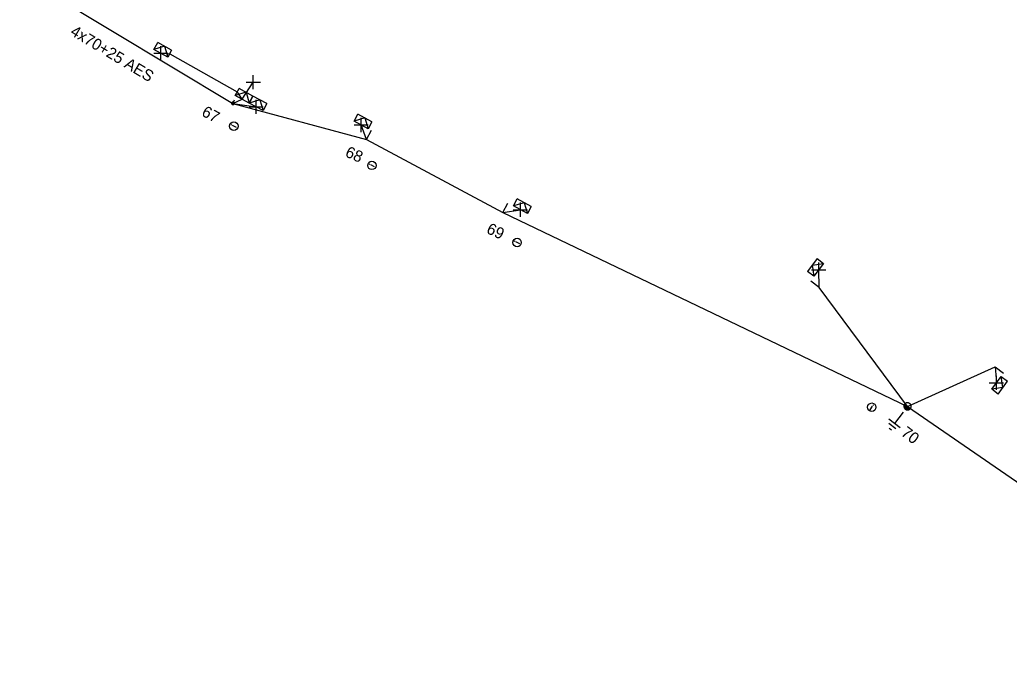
# Model space of a CAD drawing. Extents: x -540247 to -537390, y -1183887 to -1180355.
# Drawn here: x -537694.3 to -537607.2, y -1180598.3 to -1180542.1 of the extents above; entities that cross this region are included whole.
import ezdxf

# ---------------------------------------------------------------- set-up
doc = ezdxf.new("R2010")
doc.units = 0
for name, color, linetype in [('Vrstva 1', 7, 'Continuous'), ('Vrstva 10', 7, 'Continuous'), ('Vrstva 13', 7, 'Continuous'), ('Vrstva 14', 7, 'Continuous'), ('Vrstva 15', 7, 'Continuous'), ('Vrstva 2', 7, 'Continuous'), ('Vrstva 31', 7, 'Continuous'), ('Vrstva 34', 7, 'Continuous'), ('Vrstva 36', 7, 'Continuous'), ('Vrstva 4', 7, 'Continuous'), ('Vrstva 50', 7, 'Continuous'), ('Vrstva 51', 7, 'Continuous'), ('Vrstva 54', 7, 'Continuous'), ('Vrstva 59', 7, 'Continuous'), ('Vrstva 8', 7, 'Continuous'), ('Vrstva 9', 7, 'Continuous')]:
    doc.layers.add(name, color=color, linetype=linetype)

# ---------------------------------------------------------------- blocks, each defined once
blk = doc.blocks.new('NN440')
at = {"layer": 'Vrstva 2'}
for points in [[(0.63, 0), (0.63, 0.06), (0.62, 0.13), (0.6, 0.19), (0.58, 0.25), (0.55, 0.31), (0.51, 0.37), (0.47, 0.42), (0.42, 0.46), (0.37, 0.51), (0.32, 0.54), (0.26, 0.57), (0.2, 0.59), (0.13, 0.61), (0.07, 0.62), (0, 0.63), (-0.06, 0.62), (-0.13, 0.61), (-0.19, 0.59), (-0.26, 0.57), (-0.31, 0.54), (-0.37, 0.51), (-0.42, 0.46), (-0.47, 0.42), (-0.51, 0.37), (-0.54, 0.31), (-0.57, 0.25), (-0.6, 0.19), (-0.62, 0.13), (-0.63, 0.06), (-0.63, 0), (-0.63, -0.07), (-0.62, -0.14), (-0.6, -0.2), (-0.57, -0.26), (-0.54, -0.32), (-0.51, -0.37), (-0.47, -0.43), (-0.42, -0.47), (-0.37, -0.51), (-0.31, -0.55), (-0.26, -0.58), (-0.19, -0.6), (-0.13, -0.62), (-0.06, -0.63), (0, -0.63), (0.07, -0.63), (0.13, -0.62), (0.2, -0.6), (0.26, -0.58), (0.32, -0.55), (0.37, -0.51), (0.42, -0.47), (0.47, -0.43), (0.51, -0.37), (0.55, -0.32), (0.58, -0.26), (0.6, -0.2), (0.62, -0.14), (0.63, -0.07), (0.63, 0)], [(-0.63, 0), (0.63, 0)], [(-0.6, -0.18), (0.57, -0.18)], [(-0.51, -0.32), (0.5, -0.32)], [(-0.37, -0.47), (0.35, -0.47)]]:
    blk.add_lwpolyline(points, dxfattribs=at)
blk = doc.blocks.new('NN770')
at = {"layer": 'Vrstva 10'}
for p, q in [((0.002, 0.187), (0.002, 0.263)), ((0.002, -0.276), (0.002, 0.111))]:
    blk.add_line(p, q, dxfattribs=at)
blk.add_circle((0, -0.008), 0.375, dxfattribs=at)
blk = doc.blocks.new('NN800')
at = {"layer": 'Vrstva 1'}
for points in [[(-0.442, 0.442), (0.442, -0.442)], [(-0.442, -0.442), (0.442, 0.442)]]:
    blk.add_lwpolyline(points, dxfattribs=at)
blk = doc.blocks.new('NN630')
at = {"layer": 'Vrstva 9'}
for points in [[(-0.003, -0.7), (-0.703, 0)], [(-0.703, -0.7), (-0.703, 0), (0.697, 0), (0.697, -0.7)], [(-0.703, -0.7), (0.697, -0.7)], [(-0.003, -0.7), (0.697, 0)]]:
    blk.add_lwpolyline(points, dxfattribs=at)
blk = doc.blocks.new('NN810')
at = {"layer": 'Vrstva 14'}
for points in [[(0.004, -0.64), (0.004, -1.89)], [(0.629, -1.89), (-0.621, -1.89)], [(0.388, -2.2), (-0.399, -2.2)], [(0.004, -2.515), (-0.124, -2.515)], [(0.137, -2.515), (0.004, -2.515)]]:
    blk.add_lwpolyline(points, dxfattribs=at)
blk = doc.blocks.new('NN500')
at = {"layer": 'Vrstva 2'}
for points in [[(0, -0.24), (0.02, -0.23), (0.05, -0.23), (0.07, -0.22), (0.09, -0.22), (0.12, -0.2), (0.14, -0.19), (0.16, -0.18), (0.17, -0.16), (0.19, -0.14), (0.2, -0.12), (0.21, -0.1), (0.22, -0.07), (0.23, -0.05), (0.23, -0.02), (0.23, 0), (0.23, 0.02), (0.23, 0.05), (0.22, 0.07), (0.21, 0.1), (0.2, 0.12), (0.19, 0.14), (0.17, 0.16), (0.16, 0.17), (0.14, 0.19), (0.12, 0.2), (0.09, 0.21), (0.07, 0.22), (0.05, 0.23), (0.02, 0.23), (0, 0.23), (-0.03, 0.23), (-0.05, 0.23), (-0.07, 0.22), (-0.1, 0.21), (-0.12, 0.2), (-0.14, 0.19), (-0.16, 0.17), (-0.18, 0.16), (-0.19, 0.14), (-0.2, 0.12), (-0.22, 0.1), (-0.22, 0.07), (-0.23, 0.05), (-0.23, 0.02), (-0.24, 0), (-0.23, -0.02), (-0.23, -0.05), (-0.22, -0.07), (-0.22, -0.1), (-0.2, -0.12), (-0.19, -0.14), (-0.18, -0.16), (-0.16, -0.18), (-0.14, -0.19), (-0.12, -0.2), (-0.1, -0.22), (-0.07, -0.22), (-0.05, -0.23), (-0.03, -0.23), (0, -0.24)], [(0, -0.24), (0.02, -0.23), (0.05, -0.23), (0.07, -0.22), (0.09, -0.22), (0.12, -0.2), (0.14, -0.19), (0.16, -0.18), (0.17, -0.16), (0.19, -0.14), (0.2, -0.12), (0.21, -0.1), (0.22, -0.07), (0.23, -0.05), (0.23, -0.02), (0.23, 0), (0.23, 0.02), (0.23, 0.05), (0.22, 0.07), (0.21, 0.1), (0.2, 0.12), (0.19, 0.14), (0.17, 0.16), (0.16, 0.17), (0.14, 0.19), (0.12, 0.2), (0.09, 0.21), (0.07, 0.22), (0.05, 0.23), (0.02, 0.23), (0, 0.23), (-0.03, 0.23), (-0.05, 0.23), (-0.07, 0.22), (-0.1, 0.21), (-0.12, 0.2), (-0.14, 0.19), (-0.16, 0.17), (-0.18, 0.16), (-0.19, 0.14), (-0.2, 0.12), (-0.22, 0.1), (-0.22, 0.07), (-0.23, 0.05), (-0.23, 0.02), (-0.24, 0), (-0.23, -0.02), (-0.23, -0.05), (-0.22, -0.07), (-0.22, -0.1), (-0.2, -0.12), (-0.19, -0.14), (-0.18, -0.16), (-0.16, -0.18), (-0.14, -0.19), (-0.12, -0.2), (-0.1, -0.22), (-0.07, -0.22), (-0.05, -0.23), (-0.03, -0.23), (0, -0.24)], [(0, -0.21), (0.02, -0.2), (0.04, -0.2), (0.06, -0.2), (0.08, -0.19), (0.1, -0.18), (0.12, -0.17), (0.14, -0.15), (0.15, -0.14), (0.16, -0.12), (0.18, -0.1), (0.19, -0.08), (0.19, -0.06), (0.2, -0.04), (0.2, -0.02), (0.2, 0), (0.2, 0.02), (0.2, 0.04), (0.19, 0.06), (0.19, 0.08), (0.18, 0.1), (0.16, 0.12), (0.15, 0.14), (0.14, 0.15), (0.12, 0.17), (0.1, 0.18), (0.08, 0.19), (0.06, 0.19), (0.04, 0.2), (0.02, 0.2), (0, 0.2), (-0.02, 0.2), (-0.04, 0.2), (-0.06, 0.19), (-0.08, 0.19), (-0.1, 0.18), (-0.12, 0.17), (-0.14, 0.15), (-0.15, 0.14), (-0.17, 0.12), (-0.18, 0.1), (-0.19, 0.08), (-0.2, 0.06), (-0.2, 0.04), (-0.21, 0.02), (-0.21, 0), (-0.21, -0.02), (-0.2, -0.04), (-0.2, -0.06), (-0.19, -0.08), (-0.18, -0.1), (-0.17, -0.12), (-0.15, -0.14), (-0.14, -0.15), (-0.12, -0.17), (-0.1, -0.18), (-0.08, -0.19), (-0.06, -0.2), (-0.04, -0.2), (-0.02, -0.2), (0, -0.21)], [(0, -0.18), (0.02, -0.18), (0.04, -0.17), (0.05, -0.17), (0.07, -0.16), (0.09, -0.15), (0.1, -0.14), (0.12, -0.13), (0.13, -0.12), (0.14, -0.1), (0.15, -0.09), (0.16, -0.07), (0.17, -0.05), (0.17, -0.04), (0.17, -0.02), (0.17, 0), (0.17, 0.02), (0.17, 0.04), (0.17, 0.05), (0.16, 0.07), (0.15, 0.09), (0.14, 0.1), (0.13, 0.12), (0.12, 0.13), (0.1, 0.14), (0.09, 0.15), (0.07, 0.16), (0.05, 0.17), (0.04, 0.17), (0.02, 0.17), (0, 0.18), (-0.02, 0.17), (-0.04, 0.17), (-0.06, 0.17), (-0.07, 0.16), (-0.09, 0.15), (-0.1, 0.14), (-0.12, 0.13), (-0.13, 0.12), (-0.14, 0.1), (-0.15, 0.09), (-0.16, 0.07), (-0.17, 0.05), (-0.17, 0.04), (-0.18, 0.02), (-0.18, 0), (-0.18, -0.02), (-0.17, -0.04), (-0.17, -0.05), (-0.16, -0.07), (-0.15, -0.09), (-0.14, -0.1), (-0.13, -0.12), (-0.12, -0.13), (-0.1, -0.14), (-0.09, -0.15), (-0.07, -0.16), (-0.06, -0.17), (-0.04, -0.17), (-0.02, -0.18), (0, -0.18)], [(0, -0.15), (0.01, -0.15), (0.03, -0.14), (0.04, -0.14), (0.06, -0.13), (0.07, -0.13), (0.08, -0.12), (0.1, -0.11), (0.11, -0.1), (0.12, -0.09), (0.13, -0.07), (0.13, -0.06), (0.14, -0.05), (0.14, -0.03), (0.14, -0.02), (0.14, 0), (0.14, 0.01), (0.14, 0.03), (0.14, 0.04), (0.13, 0.06), (0.13, 0.07), (0.12, 0.09), (0.11, 0.1), (0.1, 0.11), (0.08, 0.12), (0.07, 0.13), (0.06, 0.13), (0.04, 0.14), (0.03, 0.14), (0.01, 0.14), (0, 0.15), (-0.02, 0.14), (-0.03, 0.14), (-0.05, 0.14), (-0.06, 0.13), (-0.07, 0.13), (-0.09, 0.12), (-0.1, 0.11), (-0.11, 0.1), (-0.12, 0.09), (-0.13, 0.07), (-0.13, 0.06), (-0.14, 0.04), (-0.14, 0.03), (-0.15, 0.01), (-0.15, 0), (-0.15, -0.02), (-0.14, -0.03), (-0.14, -0.05), (-0.13, -0.06), (-0.13, -0.07), (-0.12, -0.09), (-0.11, -0.1), (-0.1, -0.11), (-0.09, -0.12), (-0.07, -0.13), (-0.06, -0.13), (-0.05, -0.14), (-0.03, -0.14), (-0.02, -0.15), (0, -0.15)], [(0, -0.12), (0.01, -0.12), (0.02, -0.11), (0.03, -0.11), (0.05, -0.11), (0.06, -0.1), (0.07, -0.09), (0.08, -0.09), (0.09, -0.08), (0.09, -0.07), (0.1, -0.06), (0.11, -0.05), (0.11, -0.04), (0.11, -0.02), (0.11, -0.01), (0.12, 0), (0.11, 0.01), (0.11, 0.02), (0.11, 0.04), (0.11, 0.05), (0.1, 0.06), (0.09, 0.07), (0.09, 0.08), (0.08, 0.09), (0.07, 0.09), (0.06, 0.1), (0.05, 0.11), (0.03, 0.11), (0.02, 0.11), (0.01, 0.12), (0, 0.12), (-0.01, 0.12), (-0.03, 0.11), (-0.04, 0.11), (-0.05, 0.11), (-0.06, 0.1), (-0.07, 0.09), (-0.08, 0.09), (-0.09, 0.08), (-0.1, 0.07), (-0.1, 0.06), (-0.11, 0.05), (-0.11, 0.04), (-0.12, 0.02), (-0.12, 0.01), (-0.12, 0), (-0.12, -0.01), (-0.12, -0.02), (-0.11, -0.04), (-0.11, -0.05), (-0.1, -0.06), (-0.1, -0.07), (-0.09, -0.08), (-0.08, -0.09), (-0.07, -0.09), (-0.06, -0.1), (-0.05, -0.11), (-0.04, -0.11), (-0.03, -0.11), (-0.01, -0.12), (0, -0.12)], [(0, -0.09), (0.01, -0.09), (0.02, -0.09), (0.03, -0.08), (0.03, -0.08), (0.04, -0.08), (0.05, -0.07), (0.06, -0.07), (0.06, -0.06), (0.07, -0.05), (0.07, -0.04), (0.08, -0.04), (0.08, -0.03), (0.08, -0.02), (0.09, -0.01), (0.09, 0), (0.09, 0.01), (0.08, 0.02), (0.08, 0.03), (0.08, 0.03), (0.07, 0.04), (0.07, 0.05), (0.06, 0.06), (0.06, 0.06), (0.05, 0.07), (0.04, 0.07), (0.03, 0.08), (0.03, 0.08), (0.02, 0.08), (0.01, 0.09), (0, 0.09), (-0.01, 0.09), (-0.02, 0.08), (-0.03, 0.08), (-0.04, 0.08), (-0.04, 0.07), (-0.05, 0.07), (-0.06, 0.06), (-0.07, 0.06), (-0.07, 0.05), (-0.08, 0.04), (-0.08, 0.03), (-0.08, 0.03), (-0.09, 0.02), (-0.09, 0.01), (-0.09, 0), (-0.09, -0.01), (-0.09, -0.02), (-0.08, -0.03), (-0.08, -0.04), (-0.08, -0.04), (-0.07, -0.05), (-0.07, -0.06), (-0.06, -0.07), (-0.05, -0.07), (-0.04, -0.08), (-0.04, -0.08), (-0.03, -0.08), (-0.02, -0.09), (-0.01, -0.09), (0, -0.09)], [(0, -0.06), (0, -0.06), (0.01, -0.06), (0.02, -0.05), (0.02, -0.05), (0.03, -0.05), (0.03, -0.05), (0.04, -0.04), (0.04, -0.04), (0.05, -0.03), (0.05, -0.03), (0.05, -0.02), (0.05, -0.02), (0.05, -0.01), (0.06, -0.01), (0.06, 0), (0.06, 0.01), (0.05, 0.01), (0.05, 0.02), (0.05, 0.02), (0.05, 0.03), (0.05, 0.03), (0.04, 0.04), (0.04, 0.04), (0.03, 0.05), (0.03, 0.05), (0.02, 0.05), (0.02, 0.05), (0.01, 0.06), (0, 0.06), (0, 0.06), (-0.01, 0.06), (-0.01, 0.06), (-0.02, 0.05), (-0.02, 0.05), (-0.03, 0.05), (-0.03, 0.05), (-0.04, 0.04), (-0.04, 0.04), (-0.05, 0.03), (-0.05, 0.03), (-0.05, 0.02), (-0.06, 0.02), (-0.06, 0.01), (-0.06, 0.01), (-0.06, 0), (-0.06, -0.01), (-0.06, -0.01), (-0.06, -0.02), (-0.05, -0.02), (-0.05, -0.03), (-0.05, -0.03), (-0.04, -0.04), (-0.04, -0.04), (-0.03, -0.05), (-0.03, -0.05), (-0.02, -0.05), (-0.02, -0.05), (-0.01, -0.06), (-0.01, -0.06), (0, -0.06)], [(0, -0.03), (0, -0.03), (0, -0.03), (0.01, -0.03), (0.01, -0.03), (0.01, -0.02), (0.02, -0.02), (0.02, -0.02), (0.02, -0.02), (0.02, -0.02), (0.02, -0.01), (0.02, -0.01), (0.03, -0.01), (0.03, -0.01), (0.03, 0), (0.03, 0), (0.03, 0), (0.03, 0.01), (0.03, 0.01), (0.02, 0.01), (0.02, 0.01), (0.02, 0.02), (0.02, 0.02), (0.02, 0.02), (0.02, 0.02), (0.01, 0.02), (0.01, 0.02), (0.01, 0.03), (0, 0.03), (0, 0.03), (0, 0.03), (0, 0.03), (-0.01, 0.03), (-0.01, 0.03), (-0.01, 0.02), (-0.02, 0.02), (-0.02, 0.02), (-0.02, 0.02), (-0.02, 0.02), (-0.02, 0.02), (-0.03, 0.01), (-0.03, 0.01), (-0.03, 0.01), (-0.03, 0.01), (-0.03, 0), (-0.03, 0), (-0.03, 0), (-0.03, -0.01), (-0.03, -0.01), (-0.03, -0.01), (-0.03, -0.01), (-0.02, -0.02), (-0.02, -0.02), (-0.02, -0.02), (-0.02, -0.02), (-0.02, -0.02), (-0.01, -0.03), (-0.01, -0.03), (-0.01, -0.03), (0, -0.03), (0, -0.03)], [(0.23, 0), (0.7, 0)]]:
    blk.add_lwpolyline(points, dxfattribs=at)
blk = doc.blocks.new('NN510')
at = {"layer": 'Vrstva 2'}
blk.add_lwpolyline([(0.001, 0.002), (0.001, 0.939)], dxfattribs=at)

msp = doc.modelspace()

# ---------------------------------------------------------------- linework, layer by layer
at = {"layer": 'Vrstva 4'}
msp.add_lwpolyline([(-537675.507, -1180549.486), (-537674.696, -1180549.126)], dxfattribs=at)
at = {"layer": 'Vrstva 50'}
msp.add_lwpolyline([(-537694.26, -1180538.199), (-537691.624, -1180539.786), (-537675.507, -1180549.486), (-537663.756, -1180552.682), (-537651.753, -1180559.088), (-537616.15, -1180576.16), (-537591.135, -1180593.384), (-537584.357, -1180598.332)], dxfattribs=at)
at = {"layer": 'Vrstva 54'}
for points in [[(-537675.507, -1180549.486), (-537673.465, -1180549.792)], [(-537663.756, -1180552.682), (-537664.222, -1180551.39)], [(-537651.753, -1180559.088), (-537650.211, -1180558.846)]]:
    msp.add_lwpolyline(points, dxfattribs=at)
at = {"layer": 'Vrstva 59'}
for points in [[(-537674.696, -1180549.126), (-537675.092, -1180548.499), (-537681.041, -1180545.159), (-537681.854, -1180545.073)], [(-537674.696, -1180549.126), (-537673.711, -1180547.627)]]:
    msp.add_lwpolyline(points, dxfattribs=at)
at = {"layer": 'Vrstva 8'}
for points in [[(-537616.15, -1180576.16), (-537623.912, -1180565.699), (-537623.965, -1180564.136)], [(-537616.15, -1180576.16), (-537608.449, -1180572.669), (-537608.327, -1180574.095)]]:
    msp.add_lwpolyline(points, dxfattribs=at)

# ---------------------------------------------------------------- block references
at = {"layer": 'Vrstva 13', "xscale": 0.5, "yscale": 0.5}
for name, p, rotation in [('NN500', (-537675.507, -1180549.486), 64.81699996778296), ('NN440', (-537616.15, -1180576.16), -34.54923335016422)]:
    msp.add_blockref(name, p, dxfattribs=dict(at, rotation=rotation))
at = {"layer": 'Vrstva 13'}
for p, rotation in [((-537663.757, -1180552.682), -27.931052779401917), ((-537651.754, -1180559.088), -28.45128056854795), ((-537623.912, -1180565.7), 53.448638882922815), ((-537608.449, -1180572.669), -126.34501949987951)]:
    msp.add_blockref('NN510', p, dxfattribs=dict(at, rotation=rotation))
at = {"layer": 'Vrstva 15', "rotation": -37.33293883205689}
msp.add_blockref('NN810', (-537616.15, -1180576.16), dxfattribs=at)
at = {"layer": 'Vrstva 31'}
for p, rotation in [((-537681.854, -1180545.072), 151.06310566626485), ((-537674.696, -1180549.126), 150.88483893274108), ((-537673.465, -1180549.792), 152.96438056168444), ((-537664.222, -1180551.39), 152.06894722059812), ((-537650.211, -1180558.846), 151.5487195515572), ((-537623.965, -1180564.136), -126.55136119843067), ((-537608.327, -1180574.095), 53.65498055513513)]:
    msp.add_blockref('NN630', p, dxfattribs=dict(at, rotation=rotation))
at = {"layer": 'Vrstva 34'}
for p, rotation in [((-537681.854, -1180545.072), 45), ((-537673.711, -1180547.627), 45), ((-537673.465, -1180549.791), 45), ((-537664.222, -1180551.39), 44.99999995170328), ((-537650.211, -1180558.846), 45), ((-537623.965, -1180564.136), 45.00000009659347), ((-537608.327, -1180574.095), 45)]:
    msp.add_blockref('NN800', p, dxfattribs=dict(at, rotation=rotation))
at = {"layer": 'Vrstva 36'}
for p, rotation in [((-537675.431, -1180551.497), 64.82813329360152), ((-537663.282, -1180554.945), 62.01378053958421), ((-537650.515, -1180561.733), 61.521244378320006), ((-537619.296, -1180576.233), -32.949213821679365)]:
    msp.add_blockref('NN770', p, dxfattribs=dict(at, rotation=rotation))

# ---------------------------------------------------------------- texts
at = {"layer": 'Vrstva 14'}
for s, rotation, p in [('67', 331.318, (-537678.337, -1180550.525)), ('68', 336.288, (-537665.704, -1180554.134)), ('69', 335.165, (-537653.274, -1180560.873)), ('70', 322.761, (-537616.794, -1180578.647))]:
    msp.add_text(s, height=1, rotation=rotation, dxfattribs=at).set_placement(p)
at = {"layer": 'Vrstva 51'}
msp.add_text('4x70+25 AES', height=1, rotation=328.958, dxfattribs=at).set_placement((-537689.899, -1180543.409))

doc.saveas('drawing.dxf')
